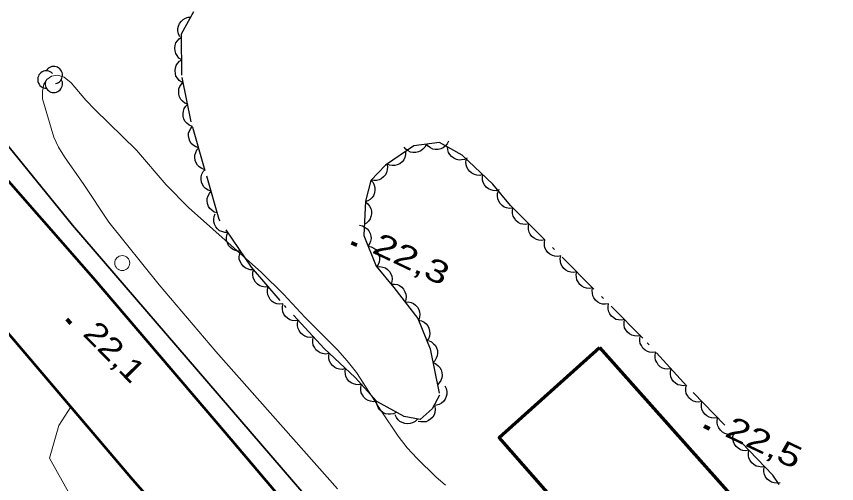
# Model space of a CAD drawing. Extents: x 356765 to 358572, y 5103174 to 5104650.
# Drawn here: x 357068.4 to 357123, y 5104021.6 to 5104052.7 of the extents above; entities that cross this region are included whole.
import ezdxf

# ---------------------------------------------------------------- set-up
doc = ezdxf.new("R2010")
doc.units = 0
doc.header["$LTSCALE"] = 0.6
doc.linetypes.add('DOT_DASHED', pattern=[7.7, 5, -1.2, 0.3, -1.2])
for name, color, linetype, lineweight in [('19', 7, 'Continuous', 13), ('2', 7, 'Continuous', 13), ('21', 7, 'Continuous', 53), ('22', 7, 'Continuous', 35), ('3', 7, 'Continuous', 140), ('31', 7, 'Continuous', 70), ('36', 7, 'Continuous', 13), ('44', 7, 'Continuous', 25)]:
    doc.layers.add(name, color=color, linetype=linetype, lineweight=lineweight)

msp = doc.modelspace()

# ---------------------------------------------------------------- linework, layer by layer
at = {"layer": '19'}
msp.add_lwpolyline([(357072.05, 5104026.74), (357071.24, 5104025.51), (357070.62, 5104023.34), (357072.42, 5104020.12), (357076.45, 5104015.51), (357079.85, 5104012.13), (357083.77, 5104008.38), (357085.85, 5104007.01), (357087.75, 5104006.38), (357089.95, 5104006.09)], dxfattribs=at)
at = {"layer": '2'}
msp.add_lwpolyline([(357096.97, 5104021.53), (357096.32, 5104022.09), (357095.08, 5104023.3), (357094.43, 5104024.01), (357093.83, 5104024.8), (357092.68, 5104026.48), (357091.05, 5104029.03), (357090.43, 5104029.82), (357089.78, 5104030.55), (357087.63, 5104032.69), (357086.19, 5104034.24), (357084.73, 5104035.68), (357079.88, 5104040.01), (357078.39, 5104041.53), (357076.41, 5104043.82), (357073.65, 5104046.53), (357073.05, 5104047.16), (357072.07, 5104048.32), (357071.6, 5104048.68), (357071.15, 5104048.82), (357070.76, 5104048.75), (357070.45, 5104048.53), (357070.25, 5104048.21), (357070.17, 5104047.76), (357070.17, 5104047.24), (357070.91, 5104044.7), (357071.23, 5104044.03), (357071.62, 5104043.38), (357072.9, 5104041.55), (357074.57, 5104039.03), (357077.92, 5104034.86), (357081.68, 5104030.43), (357089.79, 5104021.3)], dxfattribs=at)
at = {"layer": '21'}
for points in [[(357049.74, 5104064.55), (357059.41, 5104052.15), (357066.48, 5104043.37), (357073.53, 5104035.33), (357082.31, 5104025.03), (357090.61, 5104015.26), (357097.58, 5104007.28), (357102.69, 5104001.32), (357109.1, 5103993.84), (357115.62, 5103986.12), (357122.34, 5103978.36), (357128.11, 5103971.45), (357135.03, 5103963.34), (357141.1, 5103956.28), (357166.88, 5103926.08), (357186.19, 5103903.73)], [(357049.22, 5104054.8), (357051.56, 5104051.78), (357055.46, 5104046.76), (357062.02, 5104038.67), (357067.86, 5104031.67), (357076.14, 5104021.92), (357085.15, 5104011.69), (357090.68, 5104005.25), (357097.19, 5103997.43), (357102.82, 5103990.88), (357111.11, 5103981.32), (357118.26, 5103973.01), (357126.42, 5103963.3), (357145.38, 5103941.15), (357162.76, 5103921.04), (357168.24, 5103914.67), (357175.01, 5103906.8), (357180.17, 5103900.55)]]:
    msp.add_lwpolyline(points, dxfattribs=at)
at = {"layer": '22'}
msp.add_lwpolyline([(357221.36, 5103864.57), (357203.17, 5103886.01), (357184.34, 5103907.9), (357170.96, 5103923.59), (357161.12, 5103935.05), (357158.11, 5103938.34), (357149.98, 5103947.63), (357129.46, 5103972.34), (357111.79, 5103992.65), (357092.35, 5104015.36), (357072.16, 5104038.84), (357054.59, 5104060.46), (357032.27, 5104090.76), (357019.29, 5104110.68), (357013.99, 5104119.24)], dxfattribs=at)
at = {"layer": '3'}
for p, q in [((357090.71, 5104037.67), (357091.07, 5104037.5)), ((357071.77, 5104032.58), (357072.05, 5104032.3)), ((357114.17, 5104025.46), (357114.53, 5104025.29))]:
    msp.add_line(p, q, dxfattribs=at)
at = {"layer": '31'}
msp.add_lwpolyline([(357107.21, 5104030.69), (357116.44, 5104020.34), (357109.89, 5104014.34), (357107.38, 5104017.08), (357106.67, 5104016.48), (357103.8, 5104019.72), (357104.38, 5104020.33), (357100.54, 5104024.7), (357107.21, 5104030.69)], close=True, dxfattribs=at)
at = {"layer": '36'}
msp.add_circle((357075.4638, 5104036.3171), 0.5, dxfattribs=at)
at = {"layer": '44'}
for points in [[(357079.3, 5104051.37), (357079.2, 5104051.56), (357079.17, 5104051.76), (357079.16, 5104051.92), (357079.2, 5104052.09), (357079.28, 5104052.26), (357079.4, 5104052.41), (357079.51, 5104052.53), (357079.67, 5104052.61), (357079.85, 5104052.67), (357080.03, 5104052.68)], [(357079.42, 5104049.84), (357079.24, 5104049.96), (357079.11, 5104050.12), (357079.03, 5104050.26), (357078.98, 5104050.43), (357078.96, 5104050.61), (357078.99, 5104050.8), (357079.03, 5104050.96), (357079.13, 5104051.1), (357079.25, 5104051.24), (357079.4, 5104051.34)], [(357079.44, 5104048.34), (357079.26, 5104048.46), (357079.13, 5104048.62), (357079.04, 5104048.76), (357079, 5104048.93), (357078.98, 5104049.11), (357079.01, 5104049.3), (357079.05, 5104049.46), (357079.15, 5104049.6), (357079.27, 5104049.74), (357079.42, 5104049.84)], [(357079.82, 5104046.88), (357079.62, 5104046.96), (357079.47, 5104047.09), (357079.36, 5104047.21), (357079.28, 5104047.37), (357079.23, 5104047.55), (357079.22, 5104047.74), (357079.23, 5104047.9), (357079.3, 5104048.07), (357079.4, 5104048.23), (357079.52, 5104048.35)], [(357080.11, 5104045.41), (357079.92, 5104045.49), (357079.76, 5104045.62), (357079.65, 5104045.74), (357079.57, 5104045.9), (357079.52, 5104046.08), (357079.52, 5104046.27), (357079.53, 5104046.43), (357079.59, 5104046.6), (357079.69, 5104046.75), (357079.82, 5104046.88)], [(357080.55, 5104043.98), (357080.35, 5104044.04), (357080.18, 5104044.16), (357080.06, 5104044.27), (357079.97, 5104044.42), (357079.91, 5104044.59), (357079.88, 5104044.78), (357079.88, 5104044.95), (357079.94, 5104045.12), (357080.02, 5104045.28), (357080.14, 5104045.42)], [(357080.96, 5104042.53), (357080.76, 5104042.6), (357080.59, 5104042.72), (357080.47, 5104042.83), (357080.38, 5104042.98), (357080.32, 5104043.15), (357080.3, 5104043.34), (357080.3, 5104043.5), (357080.35, 5104043.67), (357080.43, 5104043.84), (357080.55, 5104043.98)], [(357095.7, 5104044.22), (357095.6, 5104044.03), (357095.47, 5104043.89), (357095.34, 5104043.78), (357095.17, 5104043.72), (357094.99, 5104043.67), (357094.8, 5104043.68), (357094.64, 5104043.7), (357094.48, 5104043.78), (357094.33, 5104043.89), (357094.21, 5104044.02)], [(357097.18, 5104044.42), (357097.09, 5104044.24), (357096.95, 5104044.09), (357096.82, 5104043.98), (357096.66, 5104043.92), (357096.48, 5104043.88), (357096.29, 5104043.88), (357096.13, 5104043.9), (357095.97, 5104043.98), (357095.82, 5104044.09), (357095.7, 5104044.22)], [(357098.42, 5104043.3), (357098.23, 5104043.21), (357098.03, 5104043.18), (357097.87, 5104043.17), (357097.7, 5104043.21), (357097.53, 5104043.29), (357097.38, 5104043.41), (357097.26, 5104043.53), (357097.18, 5104043.68), (357097.13, 5104043.86), (357097.11, 5104044.04)], [(357094.32, 5104043.74), (357094.32, 5104043.53), (357094.26, 5104043.33), (357094.19, 5104043.18), (357094.08, 5104043.05), (357093.93, 5104042.93), (357093.76, 5104042.85), (357093.61, 5104042.8), (357093.43, 5104042.8), (357093.25, 5104042.83), (357093.08, 5104042.89)], [(357093.06, 5104042.92), (357093.11, 5104042.71), (357093.09, 5104042.51), (357093.05, 5104042.35), (357092.97, 5104042.19), (357092.85, 5104042.05), (357092.7, 5104041.93), (357092.56, 5104041.85), (357092.39, 5104041.81), (357092.2, 5104041.8), (357092.03, 5104041.83)], [(357099.46, 5104042.2), (357099.25, 5104042.15), (357099.05, 5104042.17), (357098.89, 5104042.2), (357098.73, 5104042.29), (357098.59, 5104042.4), (357098.47, 5104042.55), (357098.39, 5104042.69), (357098.35, 5104042.86), (357098.33, 5104043.05), (357098.36, 5104043.23)], [(357081.37, 5104041.09), (357081.17, 5104041.16), (357081.01, 5104041.27), (357080.89, 5104041.38), (357080.8, 5104041.54), (357080.73, 5104041.71), (357080.71, 5104041.9), (357080.71, 5104042.06), (357080.76, 5104042.23), (357080.84, 5104042.4), (357080.96, 5104042.53)], [(357092.01, 5104041.84), (357092.15, 5104041.68), (357092.23, 5104041.49), (357092.28, 5104041.34), (357092.28, 5104041.16), (357092.25, 5104040.98), (357092.17, 5104040.8), (357092.08, 5104040.66), (357091.95, 5104040.55), (357091.8, 5104040.45), (357091.63, 5104040.39)], [(357100.55, 5104041.18), (357100.35, 5104041.13), (357100.14, 5104041.14), (357099.98, 5104041.18), (357099.83, 5104041.26), (357099.68, 5104041.37), (357099.57, 5104041.53), (357099.48, 5104041.67), (357099.44, 5104041.84), (357099.43, 5104042.02), (357099.46, 5104042.2)], [(357081.78, 5104039.65), (357081.59, 5104039.71), (357081.42, 5104039.83), (357081.3, 5104039.94), (357081.21, 5104040.09), (357081.14, 5104040.27), (357081.12, 5104040.46), (357081.12, 5104040.62), (357081.17, 5104040.79), (357081.26, 5104040.95), (357081.37, 5104041.09)], [(357101.44, 5104039.96), (357101.23, 5104039.94), (357101.03, 5104039.98), (357100.88, 5104040.04), (357100.73, 5104040.14), (357100.61, 5104040.27), (357100.51, 5104040.44), (357100.45, 5104040.59), (357100.43, 5104040.76), (357100.44, 5104040.95), (357100.49, 5104041.12)], [(357091.64, 5104040.39), (357091.8, 5104040.26), (357091.92, 5104040.1), (357092, 5104039.95), (357092.04, 5104039.78), (357092.05, 5104039.6), (357092.01, 5104039.41), (357091.96, 5104039.25), (357091.85, 5104039.11), (357091.72, 5104038.98), (357091.57, 5104038.89)], [(357082.5, 5104038.35), (357082.29, 5104038.35), (357082.09, 5104038.41), (357081.94, 5104038.47), (357081.81, 5104038.59), (357081.69, 5104038.73), (357081.61, 5104038.91), (357081.56, 5104039.06), (357081.56, 5104039.24), (357081.59, 5104039.42), (357081.65, 5104039.59)], [(357102.52, 5104038.92), (357102.32, 5104038.88), (357102.11, 5104038.9), (357101.95, 5104038.93), (357101.8, 5104039.02), (357101.66, 5104039.14), (357101.55, 5104039.3), (357101.47, 5104039.44), (357101.43, 5104039.61), (357101.42, 5104039.8), (357101.46, 5104039.97)], [(357091.25, 5104038.83), (357091.45, 5104038.79), (357091.63, 5104038.69), (357091.77, 5104038.6), (357091.87, 5104038.45), (357091.96, 5104038.29), (357092, 5104038.1), (357092.02, 5104037.94), (357091.98, 5104037.77), (357091.92, 5104037.6), (357091.82, 5104037.45)], [(357103.58, 5104037.86), (357103.38, 5104037.82), (357103.18, 5104037.84), (357103.02, 5104037.88), (357102.86, 5104037.97), (357102.72, 5104038.08), (357102.61, 5104038.24), (357102.53, 5104038.38), (357102.5, 5104038.55), (357102.49, 5104038.74), (357102.52, 5104038.92)], [(357083.35, 5104037.11), (357083.14, 5104037.11), (357082.94, 5104037.17), (357082.79, 5104037.24), (357082.66, 5104037.35), (357082.54, 5104037.49), (357082.46, 5104037.67), (357082.41, 5104037.82), (357082.41, 5104038), (357082.43, 5104038.18), (357082.5, 5104038.35)], [(357091.82, 5104037.45), (357092.02, 5104037.4), (357092.2, 5104037.3), (357092.33, 5104037.21), (357092.44, 5104037.07), (357092.52, 5104036.9), (357092.57, 5104036.71), (357092.58, 5104036.55), (357092.55, 5104036.38), (357092.49, 5104036.21), (357092.39, 5104036.06)], [(357104.64, 5104036.79), (357104.44, 5104036.76), (357104.24, 5104036.78), (357104.08, 5104036.82), (357103.92, 5104036.9), (357103.78, 5104037.02), (357103.67, 5104037.18), (357103.59, 5104037.32), (357103.56, 5104037.49), (357103.55, 5104037.68), (357103.58, 5104037.86)], [(357084.19, 5104035.87), (357083.98, 5104035.87), (357083.79, 5104035.93), (357083.64, 5104036), (357083.5, 5104036.11), (357083.39, 5104036.26), (357083.31, 5104036.43), (357083.25, 5104036.58), (357083.25, 5104036.76), (357083.28, 5104036.94), (357083.35, 5104037.11)], [(357105.7, 5104035.73), (357105.5, 5104035.69), (357105.3, 5104035.72), (357105.13, 5104035.75), (357104.98, 5104035.84), (357104.84, 5104035.96), (357104.73, 5104036.12), (357104.65, 5104036.26), (357104.62, 5104036.43), (357104.61, 5104036.62), (357104.64, 5104036.79)], [(357085.18, 5104034.74), (357084.97, 5104034.72), (357084.77, 5104034.76), (357084.61, 5104034.81), (357084.47, 5104034.91), (357084.34, 5104035.04), (357084.24, 5104035.2), (357084.17, 5104035.35), (357084.15, 5104035.53), (357084.16, 5104035.71), (357084.21, 5104035.89)], [(357092.4, 5104036.07), (357092.61, 5104036.09), (357092.81, 5104036.04), (357092.97, 5104035.99), (357093.11, 5104035.89), (357093.24, 5104035.75), (357093.33, 5104035.59), (357093.4, 5104035.44), (357093.42, 5104035.26), (357093.4, 5104035.08), (357093.35, 5104034.91)], [(357106.76, 5104034.67), (357106.56, 5104034.63), (357106.36, 5104034.65), (357106.19, 5104034.69), (357106.04, 5104034.78), (357105.9, 5104034.9), (357105.79, 5104035.06), (357105.71, 5104035.2), (357105.68, 5104035.37), (357105.67, 5104035.56), (357105.7, 5104035.73)], [(357086.15, 5104033.6), (357085.94, 5104033.57), (357085.74, 5104033.61), (357085.58, 5104033.66), (357085.44, 5104033.76), (357085.31, 5104033.89), (357085.21, 5104034.06), (357085.14, 5104034.21), (357085.12, 5104034.38), (357085.13, 5104034.57), (357085.18, 5104034.74)], [(357093.36, 5104034.91), (357093.57, 5104034.92), (357093.77, 5104034.88), (357093.92, 5104034.82), (357094.06, 5104034.71), (357094.18, 5104034.58), (357094.27, 5104034.41), (357094.34, 5104034.25), (357094.35, 5104034.08), (357094.33, 5104033.89), (357094.28, 5104033.72)], [(357107.82, 5104033.61), (357107.62, 5104033.57), (357107.42, 5104033.59), (357107.25, 5104033.63), (357107.1, 5104033.72), (357106.96, 5104033.84), (357106.85, 5104034), (357106.77, 5104034.14), (357106.74, 5104034.31), (357106.73, 5104034.5), (357106.76, 5104034.67)], [(357087.17, 5104032.5), (357086.97, 5104032.47), (357086.76, 5104032.5), (357086.61, 5104032.54), (357086.46, 5104032.64), (357086.32, 5104032.76), (357086.22, 5104032.92), (357086.14, 5104033.07), (357086.12, 5104033.24), (357086.12, 5104033.43), (357086.16, 5104033.6)], [(357094.28, 5104033.72), (357094.48, 5104033.74), (357094.68, 5104033.69), (357094.84, 5104033.63), (357094.98, 5104033.52), (357095.1, 5104033.39), (357095.19, 5104033.22), (357095.25, 5104033.07), (357095.27, 5104032.89), (357095.25, 5104032.71), (357095.19, 5104032.54)], [(357108.88, 5104032.55), (357108.68, 5104032.51), (357108.48, 5104032.53), (357108.31, 5104032.57), (357108.16, 5104032.66), (357108.02, 5104032.78), (357107.91, 5104032.93), (357107.83, 5104033.08), (357107.8, 5104033.25), (357107.79, 5104033.43), (357107.82, 5104033.61)], [(357088.19, 5104031.4), (357087.98, 5104031.36), (357087.78, 5104031.39), (357087.62, 5104031.44), (357087.47, 5104031.53), (357087.34, 5104031.66), (357087.23, 5104031.82), (357087.16, 5104031.97), (357087.13, 5104032.14), (357087.13, 5104032.32), (357087.17, 5104032.5)], [(357095.16, 5104032.52), (357095.37, 5104032.48), (357095.55, 5104032.38), (357095.68, 5104032.28), (357095.79, 5104032.14), (357095.87, 5104031.98), (357095.91, 5104031.79), (357095.93, 5104031.63), (357095.9, 5104031.46), (357095.83, 5104031.28), (357095.73, 5104031.13)], [(357109.94, 5104031.49), (357109.74, 5104031.45), (357109.54, 5104031.47), (357109.37, 5104031.51), (357109.22, 5104031.6), (357109.08, 5104031.72), (357108.97, 5104031.87), (357108.89, 5104032.01), (357108.86, 5104032.19), (357108.85, 5104032.37), (357108.88, 5104032.55)], [(357089.2, 5104030.29), (357089, 5104030.26), (357088.79, 5104030.29), (357088.64, 5104030.34), (357088.49, 5104030.43), (357088.35, 5104030.55), (357088.25, 5104030.72), (357088.17, 5104030.86), (357088.14, 5104031.03), (357088.15, 5104031.22), (357088.19, 5104031.4)], [(357110.96, 5104030.39), (357110.76, 5104030.36), (357110.55, 5104030.39), (357110.4, 5104030.43), (357110.25, 5104030.53), (357110.11, 5104030.65), (357110.01, 5104030.82), (357109.93, 5104030.96), (357109.91, 5104031.13), (357109.91, 5104031.32), (357109.95, 5104031.5)], [(357095.83, 5104031.16), (357096.03, 5104031.08), (357096.18, 5104030.95), (357096.3, 5104030.83), (357096.38, 5104030.68), (357096.43, 5104030.5), (357096.43, 5104030.31), (357096.42, 5104030.14), (357096.36, 5104029.98), (357096.26, 5104029.82), (357096.14, 5104029.69)], [(357090.32, 5104029.29), (357090.12, 5104029.24), (357089.91, 5104029.26), (357089.75, 5104029.29), (357089.6, 5104029.37), (357089.45, 5104029.49), (357089.34, 5104029.64), (357089.25, 5104029.78), (357089.21, 5104029.95), (357089.2, 5104030.14), (357089.23, 5104030.31)], [(357111.98, 5104029.28), (357111.77, 5104029.25), (357111.57, 5104029.28), (357111.41, 5104029.33), (357111.26, 5104029.42), (357111.13, 5104029.55), (357111.02, 5104029.71), (357110.95, 5104029.85), (357110.92, 5104030.03), (357110.92, 5104030.21), (357110.96, 5104030.39)], [(357091.42, 5104028.26), (357091.21, 5104028.22), (357091.01, 5104028.23), (357090.85, 5104028.27), (357090.69, 5104028.35), (357090.55, 5104028.46), (357090.43, 5104028.62), (357090.35, 5104028.76), (357090.31, 5104028.93), (357090.29, 5104029.11), (357090.32, 5104029.29)], [(357096.14, 5104029.69), (357096.33, 5104029.61), (357096.49, 5104029.48), (357096.6, 5104029.36), (357096.68, 5104029.21), (357096.73, 5104029.03), (357096.74, 5104028.84), (357096.72, 5104028.67), (357096.66, 5104028.51), (357096.56, 5104028.35), (357096.44, 5104028.22)], [(357112.99, 5104028.18), (357112.78, 5104028.15), (357112.58, 5104028.18), (357112.42, 5104028.22), (357112.27, 5104028.32), (357112.14, 5104028.44), (357112.03, 5104028.6), (357111.96, 5104028.75), (357111.93, 5104028.92), (357111.93, 5104029.11), (357111.98, 5104029.28)], [(357092.39, 5104027.12), (357092.18, 5104027.09), (357091.98, 5104027.12), (357091.82, 5104027.17), (357091.68, 5104027.26), (357091.54, 5104027.39), (357091.44, 5104027.55), (357091.36, 5104027.69), (357091.34, 5104027.87), (357091.34, 5104028.05), (357091.38, 5104028.23)], [(357096.93, 5104028.15), (357097.02, 5104027.96), (357097.06, 5104027.76), (357097.07, 5104027.6), (357097.02, 5104027.43), (357096.95, 5104027.26), (357096.83, 5104027.11), (357096.71, 5104026.99), (357096.56, 5104026.91), (357096.38, 5104026.85), (357096.2, 5104026.84)], [(357114.03, 5104027.1), (357113.83, 5104027.06), (357113.63, 5104027.09), (357113.47, 5104027.13), (357113.31, 5104027.22), (357113.17, 5104027.34), (357113.07, 5104027.5), (357112.99, 5104027.64), (357112.95, 5104027.81), (357112.95, 5104028), (357112.99, 5104028.17)], [(357093.7, 5104026.39), (357093.51, 5104026.29), (357093.31, 5104026.26), (357093.15, 5104026.25), (357092.97, 5104026.29), (357092.81, 5104026.37), (357092.66, 5104026.49), (357092.54, 5104026.6), (357092.46, 5104026.76), (357092.4, 5104026.93), (357092.39, 5104027.11)], [(357115.08, 5104026.02), (357114.87, 5104025.99), (357114.67, 5104026.01), (357114.51, 5104026.05), (357114.36, 5104026.14), (357114.22, 5104026.26), (357114.11, 5104026.42), (357114.03, 5104026.56), (357114, 5104026.74), (357114, 5104026.92), (357114.03, 5104027.1)], [(357096.26, 5104026.79), (357096.29, 5104026.58), (357096.26, 5104026.38), (357096.21, 5104026.22), (357096.12, 5104026.07), (357095.99, 5104025.94), (357095.83, 5104025.84), (357095.68, 5104025.76), (357095.51, 5104025.74), (357095.32, 5104025.74), (357095.15, 5104025.78)], [(357095.11, 5104025.93), (357094.96, 5104025.78), (357094.78, 5104025.69), (357094.63, 5104025.63), (357094.45, 5104025.62), (357094.27, 5104025.63), (357094.09, 5104025.7), (357093.94, 5104025.77), (357093.82, 5104025.89), (357093.7, 5104026.04), (357093.63, 5104026.21)], [(357116.12, 5104024.94), (357115.91, 5104024.91), (357115.71, 5104024.93), (357115.55, 5104024.98), (357115.4, 5104025.07), (357115.26, 5104025.19), (357115.16, 5104025.35), (357115.08, 5104025.49), (357115.05, 5104025.67), (357115.04, 5104025.85), (357115.08, 5104026.03)], [(357117.16, 5104023.86), (357116.95, 5104023.83), (357116.75, 5104023.85), (357116.59, 5104023.89), (357116.44, 5104023.99), (357116.3, 5104024.11), (357116.19, 5104024.27), (357116.12, 5104024.41), (357116.09, 5104024.58), (357116.08, 5104024.77), (357116.12, 5104024.94)], [(357118.2, 5104022.78), (357117.99, 5104022.74), (357117.79, 5104022.77), (357117.63, 5104022.81), (357117.48, 5104022.9), (357117.34, 5104023.02), (357117.23, 5104023.18), (357117.15, 5104023.33), (357117.12, 5104023.5), (357117.12, 5104023.69), (357117.16, 5104023.86)], [(357119.23, 5104021.7), (357119.03, 5104021.66), (357118.83, 5104021.69), (357118.67, 5104021.73), (357118.52, 5104021.82), (357118.38, 5104021.94), (357118.27, 5104022.1), (357118.19, 5104022.24), (357118.16, 5104022.42), (357118.16, 5104022.6), (357118.2, 5104022.78)]]:
    msp.add_lwpolyline(points, dxfattribs=at)
at = {"layer": '44', "linetype": 'DOT_DASHED'}
for points in [[(357093.53, 5104034.69), (357095.12, 5104032.63), (357095.95, 5104030.6), (357096.58, 5104027.52), (357096.08, 5104026.62), (357095.28, 5104025.9), (357094.21, 5104026.1), (357092.41, 5104027.1), (357090.95, 5104028.7), (357088.89, 5104030.63), (357085.96, 5104033.82), (357084.07, 5104036.05), (357081.91, 5104039.21), (357080.98, 5104042.46), (357080.05, 5104045.72), (357079.43, 5104048.81), (357079.4, 5104051.56), (357080.23, 5104053.05)], [(357121.78, 5104017.78), (357118.75, 5104022.2), (357115.53, 5104025.56), (357113.03, 5104028.13), (357110.11, 5104031.32), (357103.06, 5104038.38), (357101.29, 5104040.14), (357100.13, 5104041.57), (357098.07, 5104043.5), (357096.57, 5104044.34), (357094.87, 5104044.11), (357092.97, 5104042.82), (357092, 5104041.8), (357091.64, 5104040.44), (357091.53, 5104038.15), (357092.36, 5104036.12), (357093.53, 5104034.69)]]:
    msp.add_lwpolyline(points, dxfattribs=at)
at = {"layer": '44'}
for centre, start, end in [((357070.9116, 5104048.8223), 282.26917, 149.72626), ((357070.4142, 5104048.5331), 44.11537, 269.80396), ((357070.9116, 5104048.244), 166.93686, 29.62122)]:
    msp.add_arc(centre, 0.5784, start, end, dxfattribs=at)

# ---------------------------------------------------------------- texts
at = {"layer": '3'}
for s, rotation, width, p in [('22,3   ', 334.619, 1.35, (357092.01, 5104037.04)), ('22,1   ', 314.619, 1.2, (357072.78, 5104031.55)), ('22,5   ', 334.619, 1.35, (357115.47, 5104024.83))]:
    msp.add_text(s, height=1.5, rotation=rotation, dxfattribs=dict(at, width=width)).set_placement(p)

doc.saveas('drawing.dxf')
